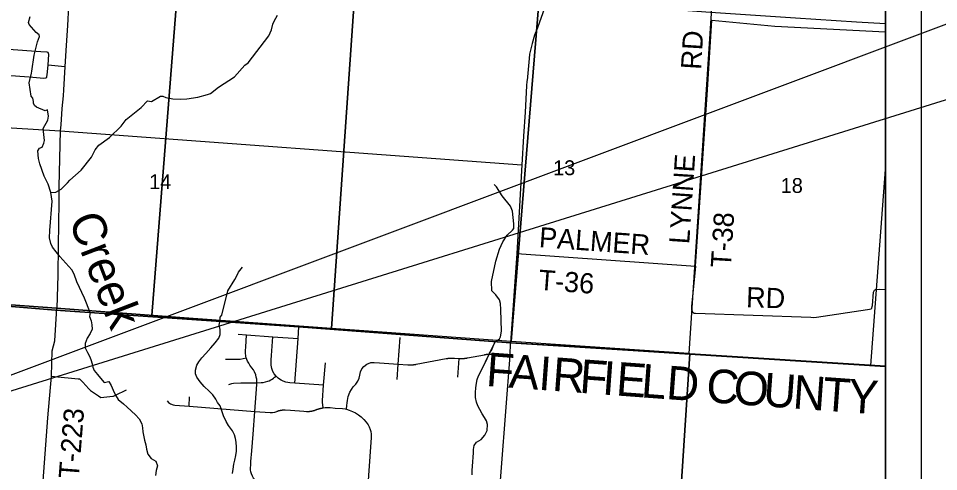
# Model space of a CAD drawing. Extents: x 0 to 34, y 0 to 22.
# Drawn here: x 6.46 to 9.049, y 17.603 to 18.88 of the extents above; entities that cross this region are included whole.
import ezdxf

# ---------------------------------------------------------------- set-up
doc = ezdxf.new("R2010")
doc.units = 0
for name, color, linetype in [('GM_X_Adjacent_County_Text', 7, 'Continuous'), ('GM_X_Corporation', 7, 'Continuous'), ('GM_X_County', 7, 'Continuous'), ('GM_X_County_Road', 7, 'Continuous'), ('GM_X_Interstate_Route', 7, 'Continuous'), ('GM_X_Minor_River', 7, 'Continuous'), ('GM_X_Minor_River_Text', 7, 'Continuous'), ('GM_X_Section_Text', 7, 'Continuous'), ('GM_X_Township_Road', 7, 'Continuous'), ('GM_X_Township_Road_Text', 7, 'Continuous'), ('SH_Data', 7, 'Continuous'), ('SH_Text', 7, 'Continuous')]:
    doc.layers.add(name, color=color, linetype=linetype)

msp = doc.modelspace()

# ---------------------------------------------------------------- linework, layer by layer
at = {"layer": 'GM_X_Corporation'}
for points in [[(6.0904, 18.0983), (6.5673, 18.064), (7.2487, 18.0119), (7.5344, 17.9901), (7.8447, 17.9665), (8.1742, 17.9461), (8.3494, 17.9349), (8.9, 17.9001), (8.9, 20.9), (4.3068, 20.9)], [(6.0906, 18.0978), (6.5646, 18.0583), (7.2489, 18.0114), (7.5346, 17.9896), (7.8449, 17.9659), (8.1744, 17.9455), (8.3496, 17.9344), (8.9, 17.8995), (8.9, 20.9), (4.3071, 20.9)], [(6.0904, 18.0983), (6.5673, 18.064), (7.2487, 18.0119), (7.5344, 17.9901), (7.8447, 17.9665), (8.1742, 17.9461), (8.3494, 17.9349), (8.9, 17.9001), (8.9, 20.4724), (8.5224, 20.4984), (8.4655, 20.5021), (7.8827, 20.5405), (6.676, 20.6183), (5.8237, 20.6711)], [(3.0167, 14.1), (8.9, 14.1), (8.9, 17.9001), (8.3494, 17.9349), (8.1742, 17.9461), (7.8447, 17.9665), (7.5344, 17.9901), (7.2487, 18.0119), (6.5673, 18.064), (6.0904, 18.0983)], [(3.0167, 14.1), (8.1011, 14.1), (8.1079, 14.1976), (8.1194, 14.3701), (8.12, 14.3767), (8.1177, 14.3813), (8.1477, 14.8503), (8.1489, 14.8684), (8.1501, 14.8865), (8.1855, 15.3822), (8.215, 15.8988), (8.2214, 15.9952), (8.3153, 17.4178), (8.3494, 17.9349), (8.1742, 17.9461), (7.8447, 17.9665), (7.5344, 17.9901), (7.2487, 18.0119), (6.5673, 18.064), (6.0904, 18.0983)], [(3.0169, 14.1), (8.9, 14.1), (8.9, 17.8995), (8.3496, 17.9344), (8.1744, 17.9455), (7.8449, 17.9659), (7.5346, 17.9896), (7.2489, 18.0114), (6.5646, 18.0583), (6.0906, 18.0978)]]:
    msp.add_lwpolyline(points, dxfattribs=at)
for points in [[(6.3967, 19.0805), (6.914, 19.0437), (6.8357, 18.0433), (6.3257, 18.0804)], [(6.914, 19.0437), (7.41, 19.0084), (7.3413, 18.0066), (6.8357, 18.0433)], [(7.41, 19.0084), (7.9283, 18.9706), (7.8463, 17.9699), (7.3413, 18.0066)], [(7.9283, 18.9706), (8.4119, 18.9377), (8.3461, 17.9359), (7.8463, 17.9699)], [(8.9, 18.4545), (8.9, 18.9043), (8.4119, 18.9377), (8.3461, 17.9359), (8.8583, 17.9025)], [(8.1011, 14.1), (8.9, 14.1), (8.9, 17.9001), (8.3494, 17.9349), (8.3153, 17.4178), (8.2214, 15.9952), (8.215, 15.8988), (8.1855, 15.3822), (8.1501, 14.8865), (8.1489, 14.8684), (8.1477, 14.8503), (8.1177, 14.3813), (8.12, 14.3767), (8.1194, 14.3701), (8.1079, 14.1976)]]:
    msp.add_lwpolyline(points, close=True, dxfattribs=at)
at = {"layer": 'GM_X_County'}
msp.add_lwpolyline([(6.0904, 18.0983), (6.5673, 18.064), (7.2487, 18.0119), (7.5344, 17.9901), (7.8447, 17.9665), (8.1742, 17.9461), (8.3494, 17.9349), (8.9, 17.9001)], dxfattribs=at)
at = {"layer": 'GM_X_County_Road'}
msp.add_lwpolyline([(6.6007, 18.9142), (6.5977, 18.8604), (6.5934, 18.79), (6.5909, 18.7438), (6.5865, 18.6784), (6.5854, 18.6619), (6.582, 18.626), (6.579, 18.5802), (6.5773, 18.5635), (6.574, 18.4067), (6.5733, 18.3632), (6.5713, 18.2398), (6.5709, 18.1571), (6.5676, 18.0635)], dxfattribs=at)
at = {"layer": 'GM_X_Interstate_Route'}
msp.add_lwpolyline([(6.3995, 19.0399), (6.6039, 19.0257), (6.9106, 19.0042), (7.1722, 18.9854), (7.3938, 18.9698), (7.626, 18.9534), (7.8578, 18.937), (7.9472, 18.9307), (8.1146, 18.9188), (8.4071, 18.8978), (8.647, 18.8813), (8.8185, 18.8708), (8.9, 18.8652)], dxfattribs=at)
at = {"layer": 'GM_X_Minor_River'}
for points in [[(6.6616, 18.0516), (6.6462, 18.0924), (6.624, 18.1376), (6.6168, 18.1593), (6.6104, 18.1715), (6.576, 18.2095), (6.556, 18.2354), (6.5515, 18.2456), (6.5477, 18.262), (6.5485, 18.2828), (6.5544, 18.3649), (6.551, 18.3892), (6.5431, 18.4135), (6.5326, 18.4355), (6.5202, 18.4705), (6.5164, 18.4857), (6.5142, 18.5066), (6.5195, 18.5145), (6.5263, 18.5176), (6.5316, 18.5282), (6.5332, 18.5365), (6.5298, 18.5703), (6.5424, 18.5931), (6.5447, 18.6048), (6.5417, 18.6227), (6.5348, 18.6193), (6.5106, 18.6304), (6.5053, 18.6349), (6.5023, 18.641), (6.5027, 18.6459), (6.5005, 18.6551), (6.4959, 18.6611), (6.4903, 18.6984), (6.4964, 18.7253), (6.498, 18.7318), (6.5045, 18.7765), (6.5133, 18.8141), (6.519, 18.8289), (6.5186, 18.8342), (6.5096, 18.8399), (6.4899, 18.8624), (6.4884, 18.8681), (6.4926, 18.8855)], [(6.5503, 18.3915), (6.5518, 18.3899), (6.5654, 18.3906), (6.5802, 18.3993), (6.5984, 18.4168), (6.6045, 18.4247), (6.6364, 18.4528), (6.6656, 18.4895), (6.6762, 18.51), (6.6857, 18.5229), (6.7157, 18.5448), (6.7491, 18.5767), (6.7635, 18.5956), (6.8049, 18.6289), (6.8227, 18.6483), (6.8348, 18.6463), (6.8598, 18.6611), (6.8663, 18.6607), (6.875, 18.6569), (6.8943, 18.6534), (6.9155, 18.6522), (6.934, 18.6533), (6.9651, 18.6582), (6.9916, 18.6653), (7, 18.6687), (7.0231, 18.6861), (7.0678, 18.7153), (7.0974, 18.7486), (7.1062, 18.7551), (7.1646, 18.8312), (7.1723, 18.8475), (7.1761, 18.8635), (7.1791, 18.8726), (7.1886, 18.8896)], [(7.801, 17.9694), (7.8138, 17.977), (7.8165, 17.9831), (7.8196, 17.9986), (7.8178, 18.0598), (7.8163, 18.0769), (7.8133, 18.0875), (7.8031, 18.1012), (7.7921, 18.1122), (7.7911, 18.1392), (7.8029, 18.1961), (7.8132, 18.2303), (7.8227, 18.2504), (7.8356, 18.2697), (7.8504, 18.2837), (7.8539, 18.2886), (7.8539, 18.2951), (7.8535, 18.3015), (7.8502, 18.3372), (7.8445, 18.3513), (7.8215, 18.3798), (7.8052, 18.4057), (7.7988, 18.4122)], [(7.0267, 18.0253), (7.0278, 18.038), (7.0324, 18.0444), (7.0492, 18.1131), (7.0686, 18.145), (7.0758, 18.1564), (7.0796, 18.1655), (7.0906, 18.1795)], [(6.6616, 18.0516), (6.66, 18.0401), (6.6645, 18.0279), (6.6662, 18.0165), (6.6676, 18.0051), (6.6618, 17.9923), (6.6533, 17.9795), (6.6475, 17.9647), (6.6477, 17.9522), (6.654, 17.9392), (6.66, 17.9285), (6.664, 17.919), (6.6673, 17.9072), (6.6695, 17.8973), (6.6732, 17.8878), (6.6825, 17.8767), (6.6911, 17.8667), (6.7016, 17.8544), (6.7141, 17.857), (6.7212, 17.8463), (6.7267, 17.8329), (6.733, 17.8184), (6.7408, 17.8062), (6.7559, 17.7943), (6.7656, 17.7847), (6.7893, 17.7632), (6.8001, 17.7517), (6.8072, 17.7379), (6.8089, 17.7265), (6.8096, 17.7155), (6.8128, 17.7018), (6.815, 17.6919), (6.8183, 17.6786), (6.8204, 17.6664), (6.8244, 17.6527), (6.8338, 17.6405), (6.8462, 17.6327), (6.851, 17.6198), (6.8478, 17.6065), (6.8458, 17.5929)], [(7.0625, 17.5982), (7.0641, 17.6103), (7.0662, 17.624), (7.069, 17.6357), (7.0721, 17.649), (7.0734, 17.6607), (7.0739, 17.6725), (7.0729, 17.6866), (7.0704, 17.6968), (7.0675, 17.7071), (7.0619, 17.7182), (7.0507, 17.7335), (7.0444, 17.7446), (7.037, 17.7602), (7.0329, 17.7716), (7.0274, 17.7888), (7.0203, 17.7983), (7.0155, 17.8079), (7.0069, 17.8201), (6.9968, 17.8297), (6.9829, 17.8435), (6.971, 17.8562), (6.962, 17.8692), (6.9583, 17.8791), (6.9577, 17.8894), (6.962, 17.903), (6.9678, 17.9128), (6.9758, 17.9237), (6.987, 17.9361), (7.0015, 17.9523), (7.0134, 17.9658), (7.0238, 17.979), (7.0277, 17.99), (7.0279, 18.0037), (7.025, 18.0162), (7.0267, 18.0253)], [(7.7364, 17.5939), (7.7365, 17.6064), (7.7378, 17.6189), (7.7387, 17.631), (7.7395, 17.6439), (7.7401, 17.6565), (7.7409, 17.666), (7.7426, 17.6766), (7.7491, 17.6867), (7.7617, 17.6938), (7.7724, 17.7062), (7.779, 17.7195), (7.7799, 17.7365), (7.7766, 17.7464), (7.7714, 17.756), (7.7651, 17.7663), (7.7584, 17.7785), (7.7529, 17.7884), (7.7492, 17.7995), (7.7463, 17.8121), (7.7461, 17.8265), (7.7466, 17.8398), (7.7486, 17.8526), (7.751, 17.8633), (7.7545, 17.8731), (7.7611, 17.8852), (7.801, 17.9694)], [(7.7681, 17.8999), (7.7735, 17.9097), (7.7789, 17.9218), (7.7859, 17.9369), (7.7917, 17.9467), (7.7975, 17.9611)]]:
    msp.add_lwpolyline(points, dxfattribs=at)
at = {"layer": 'GM_X_Township_Road'}
for p, q in [((6.5773, 18.5635), (7.876, 18.4678)), ((7.876, 18.4678), (7.8623, 18.2174)), ((7.8623, 18.2174), (7.8449, 17.9659)), ((7.6966, 17.8694), (7.7005, 17.9222)), ((7.7997, 17.9339), (7.8439, 17.9308)), ((6.94, 17.7876), (6.9415, 17.8142))]:
    msp.add_line(p, q, dxfattribs=at)
for points in [[(7.9907, 19.1106), (7.9891, 19.0847), (7.9869, 19.0632), (7.9829, 19.0385), (7.9768, 19.0145), (7.9715, 18.9979), (7.9641, 18.9765), (7.9538, 18.9505), (7.9472, 18.9307), (7.9351, 18.8956), (7.9202, 18.8539), (7.912, 18.8331), (7.9053, 18.8095), (7.9015, 18.7947), (7.8978, 18.7791), (7.8971, 18.7669), (7.891, 18.705), (7.8908, 18.703)], [(8.3649, 18.182), (8.3986, 18.6786), (8.4108, 18.8752)], [(8.4108, 18.8752), (8.5883, 18.8584), (8.9, 18.842)], [(6.5909, 18.7438), (6.5431, 18.7481), (6.5441, 18.7638), (6.545, 18.7783), (6.5446, 18.7815), (6.5435, 18.7841), (6.5404, 18.7852), (6.5226, 18.7863), (6.432, 18.7926)], [(6.425, 18.72), (6.4898, 18.7153), (6.5317, 18.7121), (6.5374, 18.7123), (6.5394, 18.7141), (6.5401, 18.7164), (6.5406, 18.7211), (6.5431, 18.7481)], [(4.3588, 18.7211), (4.6089, 18.7022), (4.6446, 18.6995), (4.7336, 18.6925), (4.7612, 18.6909), (4.9046, 18.6801), (5.1086, 18.6685), (5.1411, 18.6657), (5.1701, 18.6632), (5.1983, 18.6624), (5.4964, 18.642), (6.1506, 18.5908), (6.3173, 18.5789), (6.5773, 18.5635)], [(7.8908, 18.703), (7.8894, 18.6898), (7.886, 18.616), (7.8809, 18.5484), (7.876, 18.4678)], [(7.8623, 18.2174), (8.3649, 18.182), (8.3541, 18.0686), (8.3541, 18.0602), (8.3553, 18.0565), (8.3564, 18.053), (8.3583, 18.0512), (8.3614, 18.0496), (8.3656, 18.0497), (8.6898, 18.0381), (8.6978, 18.0378), (8.7057, 18.0386), (8.8487, 18.0605), (8.8548, 18.0609), (8.859, 18.062), (8.8609, 18.064), (8.8627, 18.0681), (8.8631, 18.0716), (8.8664, 18.1088), (8.8675, 18.1122), (8.8686, 18.1145), (8.8705, 18.1157), (8.872, 18.1168), (8.8754, 18.1165), (8.8829, 18.1176), (8.9, 18.1166)], [(6.528, 17.552), (6.5428, 17.755), (6.553, 17.872), (6.5547, 17.9434), (6.5622, 17.9715), (6.5676, 18.0635)], [(7.2379, 17.8523), (7.2466, 17.9783), (7.2489, 18.0114)], [(7.0779, 17.9903), (7.1015, 17.9885), (7.1759, 17.9827), (7.2466, 17.9783)], [(7.1252, 17.7731), (7.1308, 17.8484), (7.1308, 17.8539), (7.1303, 17.8638), (7.1293, 17.8698), (7.1277, 17.8757), (7.1242, 17.8843), (7.121, 17.8903), (7.117, 17.896), (7.1115, 17.9034), (7.1079, 17.9087), (7.1047, 17.9144), (7.1027, 17.9189), (7.1008, 17.9241), (7.1, 17.9289), (7.0995, 17.9316), (7.099, 17.935), (7.0988, 17.9393), (7.099, 17.9449), (7.0995, 17.9539), (7.1015, 17.9885)], [(7.3187, 17.8468), (7.2379, 17.8523), (7.2238, 17.8533), (7.218, 17.854), (7.2126, 17.8552), (7.2051, 17.8579), (7.199, 17.8608), (7.1949, 17.8636), (7.1906, 17.867), (7.1848, 17.8718), (7.1796, 17.8784), (7.1759, 17.8853), (7.1729, 17.894), (7.1711, 17.903), (7.1707, 17.9092), (7.1711, 17.9184), (7.172, 17.9307), (7.1759, 17.9827)], [(7.5252, 17.863), (7.5285, 17.9065), (7.5341, 17.9816)], [(7.8067, 17.4568), (7.8439, 17.9308), (7.8449, 17.9659)], [(7.0423, 17.9204), (7.0469, 17.9203), (7.0529, 17.92), (7.0608, 17.9199), (7.0695, 17.9198), (7.0765, 17.9198), (7.0809, 17.92), (7.0842, 17.9205), (7.0922, 17.922), (7.1008, 17.9241)], [(7.5285, 17.9065), (7.5554, 17.9045), (7.5561, 17.9044), (7.5569, 17.9044), (7.5576, 17.9043), (7.5584, 17.9043), (7.5592, 17.9043), (7.5599, 17.9043), (7.5607, 17.9042), (7.5614, 17.9042), (7.5622, 17.9042), (7.5629, 17.9042), (7.5637, 17.9042), (7.5645, 17.9042), (7.5652, 17.9043), (7.566, 17.9043), (7.5667, 17.9043), (7.5675, 17.9044), (7.5682, 17.9044), (7.569, 17.9045), (7.5698, 17.9045), (7.5705, 17.9046), (7.5713, 17.9046), (7.572, 17.9047), (7.5728, 17.9048), (7.5735, 17.9049), (7.5743, 17.905), (7.575, 17.9051), (7.5758, 17.9052), (7.5765, 17.9053), (7.5773, 17.9054), (7.578, 17.9055), (7.5788, 17.9057), (7.5795, 17.9058), (7.6633, 17.9217), (7.664, 17.9219), (7.6648, 17.922), (7.6655, 17.9221), (7.6663, 17.9222), (7.667, 17.9224), (7.6678, 17.9225), (7.6685, 17.9226), (7.6693, 17.9227), (7.67, 17.9228), (7.6708, 17.9228), (7.6715, 17.9229), (7.6723, 17.923), (7.673, 17.9231), (7.6738, 17.9231), (7.6746, 17.9232), (7.6753, 17.9232), (7.6761, 17.9233), (7.6768, 17.9233), (7.6776, 17.9233), (7.6783, 17.9234), (7.6791, 17.9234), (7.6799, 17.9234), (7.6806, 17.9234), (7.6814, 17.9234), (7.6821, 17.9234), (7.6829, 17.9234), (7.6836, 17.9234), (7.6844, 17.9233), (7.6852, 17.9233), (7.6859, 17.9233), (7.6867, 17.9232), (7.6874, 17.9232), (7.7005, 17.9222)], [(7.7005, 17.9222), (7.7012, 17.9222), (7.702, 17.9221), (7.7028, 17.9221), (7.7035, 17.9221), (7.7043, 17.9221), (7.705, 17.9221), (7.7058, 17.9221), (7.7065, 17.9221), (7.7073, 17.9221), (7.7081, 17.9221), (7.7088, 17.9221), (7.7096, 17.9221), (7.7103, 17.9222), (7.7111, 17.9222), (7.7118, 17.9223), (7.7126, 17.9223), (7.7134, 17.9224), (7.7141, 17.9224), (7.7149, 17.9225), (7.7156, 17.9226), (7.7164, 17.9227), (7.7171, 17.9228), (7.7179, 17.9228), (7.7186, 17.9229), (7.7194, 17.9231), (7.7201, 17.9232), (7.7209, 17.9233), (7.7216, 17.9234), (7.7224, 17.9235), (7.7235, 17.9237), (7.7712, 17.9328), (7.772, 17.9329), (7.7727, 17.9331), (7.7735, 17.9332), (7.7742, 17.9333), (7.775, 17.9334), (7.7757, 17.9336), (7.7765, 17.9337), (7.7772, 17.9338), (7.778, 17.9338), (7.7787, 17.9339), (7.7795, 17.934), (7.7802, 17.9341), (7.781, 17.9341), (7.7818, 17.9342), (7.7825, 17.9343), (7.7833, 17.9343), (7.784, 17.9343), (7.7848, 17.9344), (7.7855, 17.9344), (7.7863, 17.9344), (7.7871, 17.9345), (7.7878, 17.9345), (7.7886, 17.9345), (7.7893, 17.9345), (7.7901, 17.9345), (7.7908, 17.9345), (7.7916, 17.9344), (7.7924, 17.9344), (7.7931, 17.9344), (7.7939, 17.9343), (7.7946, 17.9343), (7.7957, 17.9342), (7.7997, 17.9339)], [(7.7907, 17.8623), (7.791, 17.8629), (7.7913, 17.8636), (7.7916, 17.8643), (7.7919, 17.865), (7.7922, 17.8657), (7.7925, 17.8664), (7.7928, 17.8671), (7.793, 17.8678), (7.7933, 17.8685), (7.7935, 17.8693), (7.7938, 17.87), (7.794, 17.8707), (7.7942, 17.8714), (7.7944, 17.8722), (7.7946, 17.8729), (7.7947, 17.8736), (7.7949, 17.8744), (7.795, 17.8751), (7.7952, 17.8759), (7.7953, 17.8766), (7.7954, 17.8774), (7.7955, 17.8781), (7.7956, 17.8789), (7.7957, 17.8796), (7.7958, 17.8804), (7.7959, 17.8811), (7.7997, 17.9339)], [(7.3176, 17.7829), (7.3155, 17.7988), (7.3154, 17.8034), (7.3187, 17.8468), (7.3239, 17.91)], [(7.3834, 17.7789), (7.3842, 17.7894), (7.3849, 17.7974), (7.3855, 17.8039), (7.3879, 17.8153), (7.3927, 17.8275), (7.3969, 17.8348), (7.402, 17.8418), (7.4096, 17.8501), (7.4153, 17.8581), (7.4189, 17.8663), (7.4209, 17.875), (7.4226, 17.8842), (7.4264, 17.8929), (7.4314, 17.8994), (7.4406, 17.9065), (7.4515, 17.9105), (7.4612, 17.9112), (7.4758, 17.9101), (7.5285, 17.9065)], [(6.553, 17.872), (6.5613, 17.8713), (6.6283, 17.8652), (6.6314, 17.8649), (6.6408, 17.8549), (6.6581, 17.8365), (6.6624, 17.832), (6.6712, 17.8261), (6.6852, 17.8167), (6.6915, 17.8125), (6.7006, 17.8134), (6.7258, 17.8159), (6.7276, 17.8161), (6.741, 17.8227), (6.7561, 17.8301), (6.7637, 17.8338)], [(7.1308, 17.8539), (7.1428, 17.8544), (7.149, 17.8548), (7.1552, 17.8559), (7.1614, 17.8578), (7.1655, 17.8593), (7.1698, 17.8617), (7.1739, 17.8642), (7.1773, 17.8666), (7.1808, 17.869), (7.1848, 17.8718)], [(7.0519, 17.8491), (7.0578, 17.851), (7.0608, 17.8519), (7.0653, 17.8527), (7.0853, 17.8539), (7.1308, 17.8539)], [(6.8784, 17.8027), (6.8826, 17.7983), (6.8882, 17.7947), (6.8949, 17.7919), (6.8999, 17.7907), (6.94, 17.7876), (7.1252, 17.7731), (7.1678, 17.7701), (7.1687, 17.7701), (7.1749, 17.7703), (7.1811, 17.7711), (7.1869, 17.7731), (7.1875, 17.7733), (7.1882, 17.7735), (7.1889, 17.7738), (7.19, 17.7741), (7.1907, 17.7744), (7.1914, 17.7746), (7.1921, 17.7748), (7.1928, 17.7751), (7.1936, 17.7753), (7.1943, 17.7755), (7.195, 17.7756), (7.1958, 17.7758), (7.1965, 17.776), (7.1973, 17.7762), (7.198, 17.7763), (7.1987, 17.7764), (7.1995, 17.7766), (7.2002, 17.7767), (7.201, 17.7768), (7.2017, 17.7769), (7.2025, 17.777), (7.2032, 17.7771), (7.204, 17.7771), (7.2047, 17.7772), (7.2055, 17.7772), (7.2063, 17.7773), (7.207, 17.7773), (7.2078, 17.7773), (7.2085, 17.7773), (7.2104, 17.7777), (7.2254, 17.7763), (7.263, 17.7737), (7.2708, 17.7732), (7.2717, 17.7732), (7.2725, 17.7731), (7.2732, 17.7731), (7.274, 17.7731), (7.2748, 17.7731), (7.2755, 17.7731), (7.2763, 17.7731), (7.277, 17.7731), (7.2778, 17.7732), (7.2785, 17.7732), (7.2793, 17.7733), (7.2801, 17.7733), (7.2808, 17.7734), (7.2816, 17.7735), (7.2823, 17.7736), (7.2831, 17.7737), (7.2838, 17.7738), (7.2846, 17.7739), (7.2853, 17.7741), (7.286, 17.7742), (7.2868, 17.7744), (7.2875, 17.7745), (7.2883, 17.7747), (7.289, 17.7749), (7.2897, 17.7751), (7.2905, 17.7753), (7.2912, 17.7755), (7.2919, 17.7757), (7.2926, 17.776), (7.2933, 17.7762), (7.2941, 17.7765), (7.2948, 17.7767), (7.2955, 17.777), (7.2964, 17.7774), (7.2971, 17.7776), (7.2978, 17.7779), (7.2986, 17.7782), (7.2993, 17.7784), (7.3, 17.7787), (7.3007, 17.7789), (7.3014, 17.7792), (7.3021, 17.7794), (7.3029, 17.7796), (7.3036, 17.7798), (7.3043, 17.7801), (7.305, 17.7803), (7.3058, 17.7805), (7.3065, 17.7807), (7.3072, 17.7809), (7.308, 17.781), (7.3087, 17.7812), (7.3094, 17.7814), (7.3102, 17.7816), (7.3109, 17.7817), (7.3117, 17.7819), (7.3124, 17.782), (7.3131, 17.7822), (7.3139, 17.7823), (7.3146, 17.7825), (7.3154, 17.7826), (7.3161, 17.7827), (7.3169, 17.7828), (7.3176, 17.7829), (7.3235, 17.7836), (7.3308, 17.7839), (7.3375, 17.7837), (7.3515, 17.7825), (7.3722, 17.7808), (7.3791, 17.7798), (7.3834, 17.7789), (7.391, 17.7767), (7.4004, 17.7731), (7.4082, 17.7691), (7.4165, 17.7638), (7.4239, 17.7579), (7.4321, 17.7498), (7.438, 17.7429), (7.4436, 17.7356), (7.4469, 17.7299), (7.4501, 17.7222), (7.4517, 17.716), (7.4527, 17.709), (7.4527, 17.6997), (7.4377, 17.4852)], [(7.1387, 17.564), (7.1336, 17.5698), (7.1289, 17.5751), (7.1249, 17.58), (7.1213, 17.5852), (7.1184, 17.5908), (7.116, 17.5967), (7.1142, 17.6027), (7.1133, 17.6084), (7.1131, 17.6136), (7.1135, 17.6217), (7.1141, 17.6322), (7.1163, 17.662), (7.1202, 17.7086), (7.1252, 17.7731)]]:
    msp.add_lwpolyline(points, dxfattribs=at)
at = {"layer": 'SH_Data'}
for p, q in [((9, 21), (9, 14)), ((8.9, 20.9), (8.9, 14.1))]:
    msp.add_line(p, q, dxfattribs=at)
at = {"layer": 'SH_Text'}
msp.add_lwpolyline([(9.625, 19.0732), (9.625, 18.8232), (5.7267, 17.6088)], close=True, dxfattribs=at)

# ---------------------------------------------------------------- texts
at = {"layer": 'GM_X_Adjacent_County_Text'}
for s, rotation, p in [('F', 355.8052, (7.7739, 17.8449)), ('A', 355.8044, (7.8379, 17.8402)), ('I', 355.8053, (7.9214, 17.8341)), ('R', 355.8061, (7.96, 17.8313)), ('F', 355.8038, (8.0369, 17.8256)), ('I', 355.8067, (8.1009, 17.8209)), ('E', 355.8036, (8.1396, 17.8181)), ('L', 355.8055, (8.2102, 17.8129)), ('D', 355.8044, (8.2809, 17.8078)), ('C', 355.8045, (8.3931, 17.7995)), ('O', 355.8059, (8.4699, 17.7939)), ('U', 355.8065, (8.5535, 17.7878)), ('N', 355.8177, (8.637, 17.7816)), ('T', 355.862, (8.7206, 17.7755)), ('Y', 356.1003, (8.7917, 17.7704))]:
    msp.add_text(s, height=0.0947, rotation=rotation, dxfattribs=at).set_placement(p)
at = {"layer": 'GM_X_Minor_River_Text'}
msp.add_text('Creek', height=0.09472, rotation=290.9911, dxfattribs=at).set_placement((6.5999, 18.3132))
at = {"layer": 'GM_X_Section_Text'}
for s, p in [('13', (7.9644, 18.4384)), ('14', (6.8278, 18.3991)), ('18', (8.6049, 18.3884))]:
    msp.add_text(s, height=0.04186, rotation=0, dxfattribs=at).set_placement(p)
at = {"layer": 'GM_X_Township_Road_Text'}
for s, rotation, p in [('RD', 86.5467, (8.3807, 18.7346)), ('LYNNE', 86.1316, (8.3474, 18.2431)), ('T-38', 86.4464, (8.4645, 18.1764)), ('PALMER', 355.9261, (7.9235, 18.2357)), ('T-36', 355.737, (7.9221, 18.1158)), ('RD', 358.0262, (8.5069, 18.0666)), ('T-223', 85.4937, (6.6294, 17.5821))]:
    msp.add_text(s, height=0.05682, rotation=rotation, dxfattribs=at).set_placement(p)

doc.saveas('drawing.dxf')
